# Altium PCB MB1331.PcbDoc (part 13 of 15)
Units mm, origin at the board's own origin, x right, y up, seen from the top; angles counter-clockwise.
Board outline 169.25 x 173.25 mm, 6 copper layers (Top Layer, Signal Layer 1, Signal Layer 2, Signal Layer 3, Signal Layer 4, Bottom Layer), stack 1.556 mm thick; 871 components, 699 nets, 3244 pads, 2370 vias.
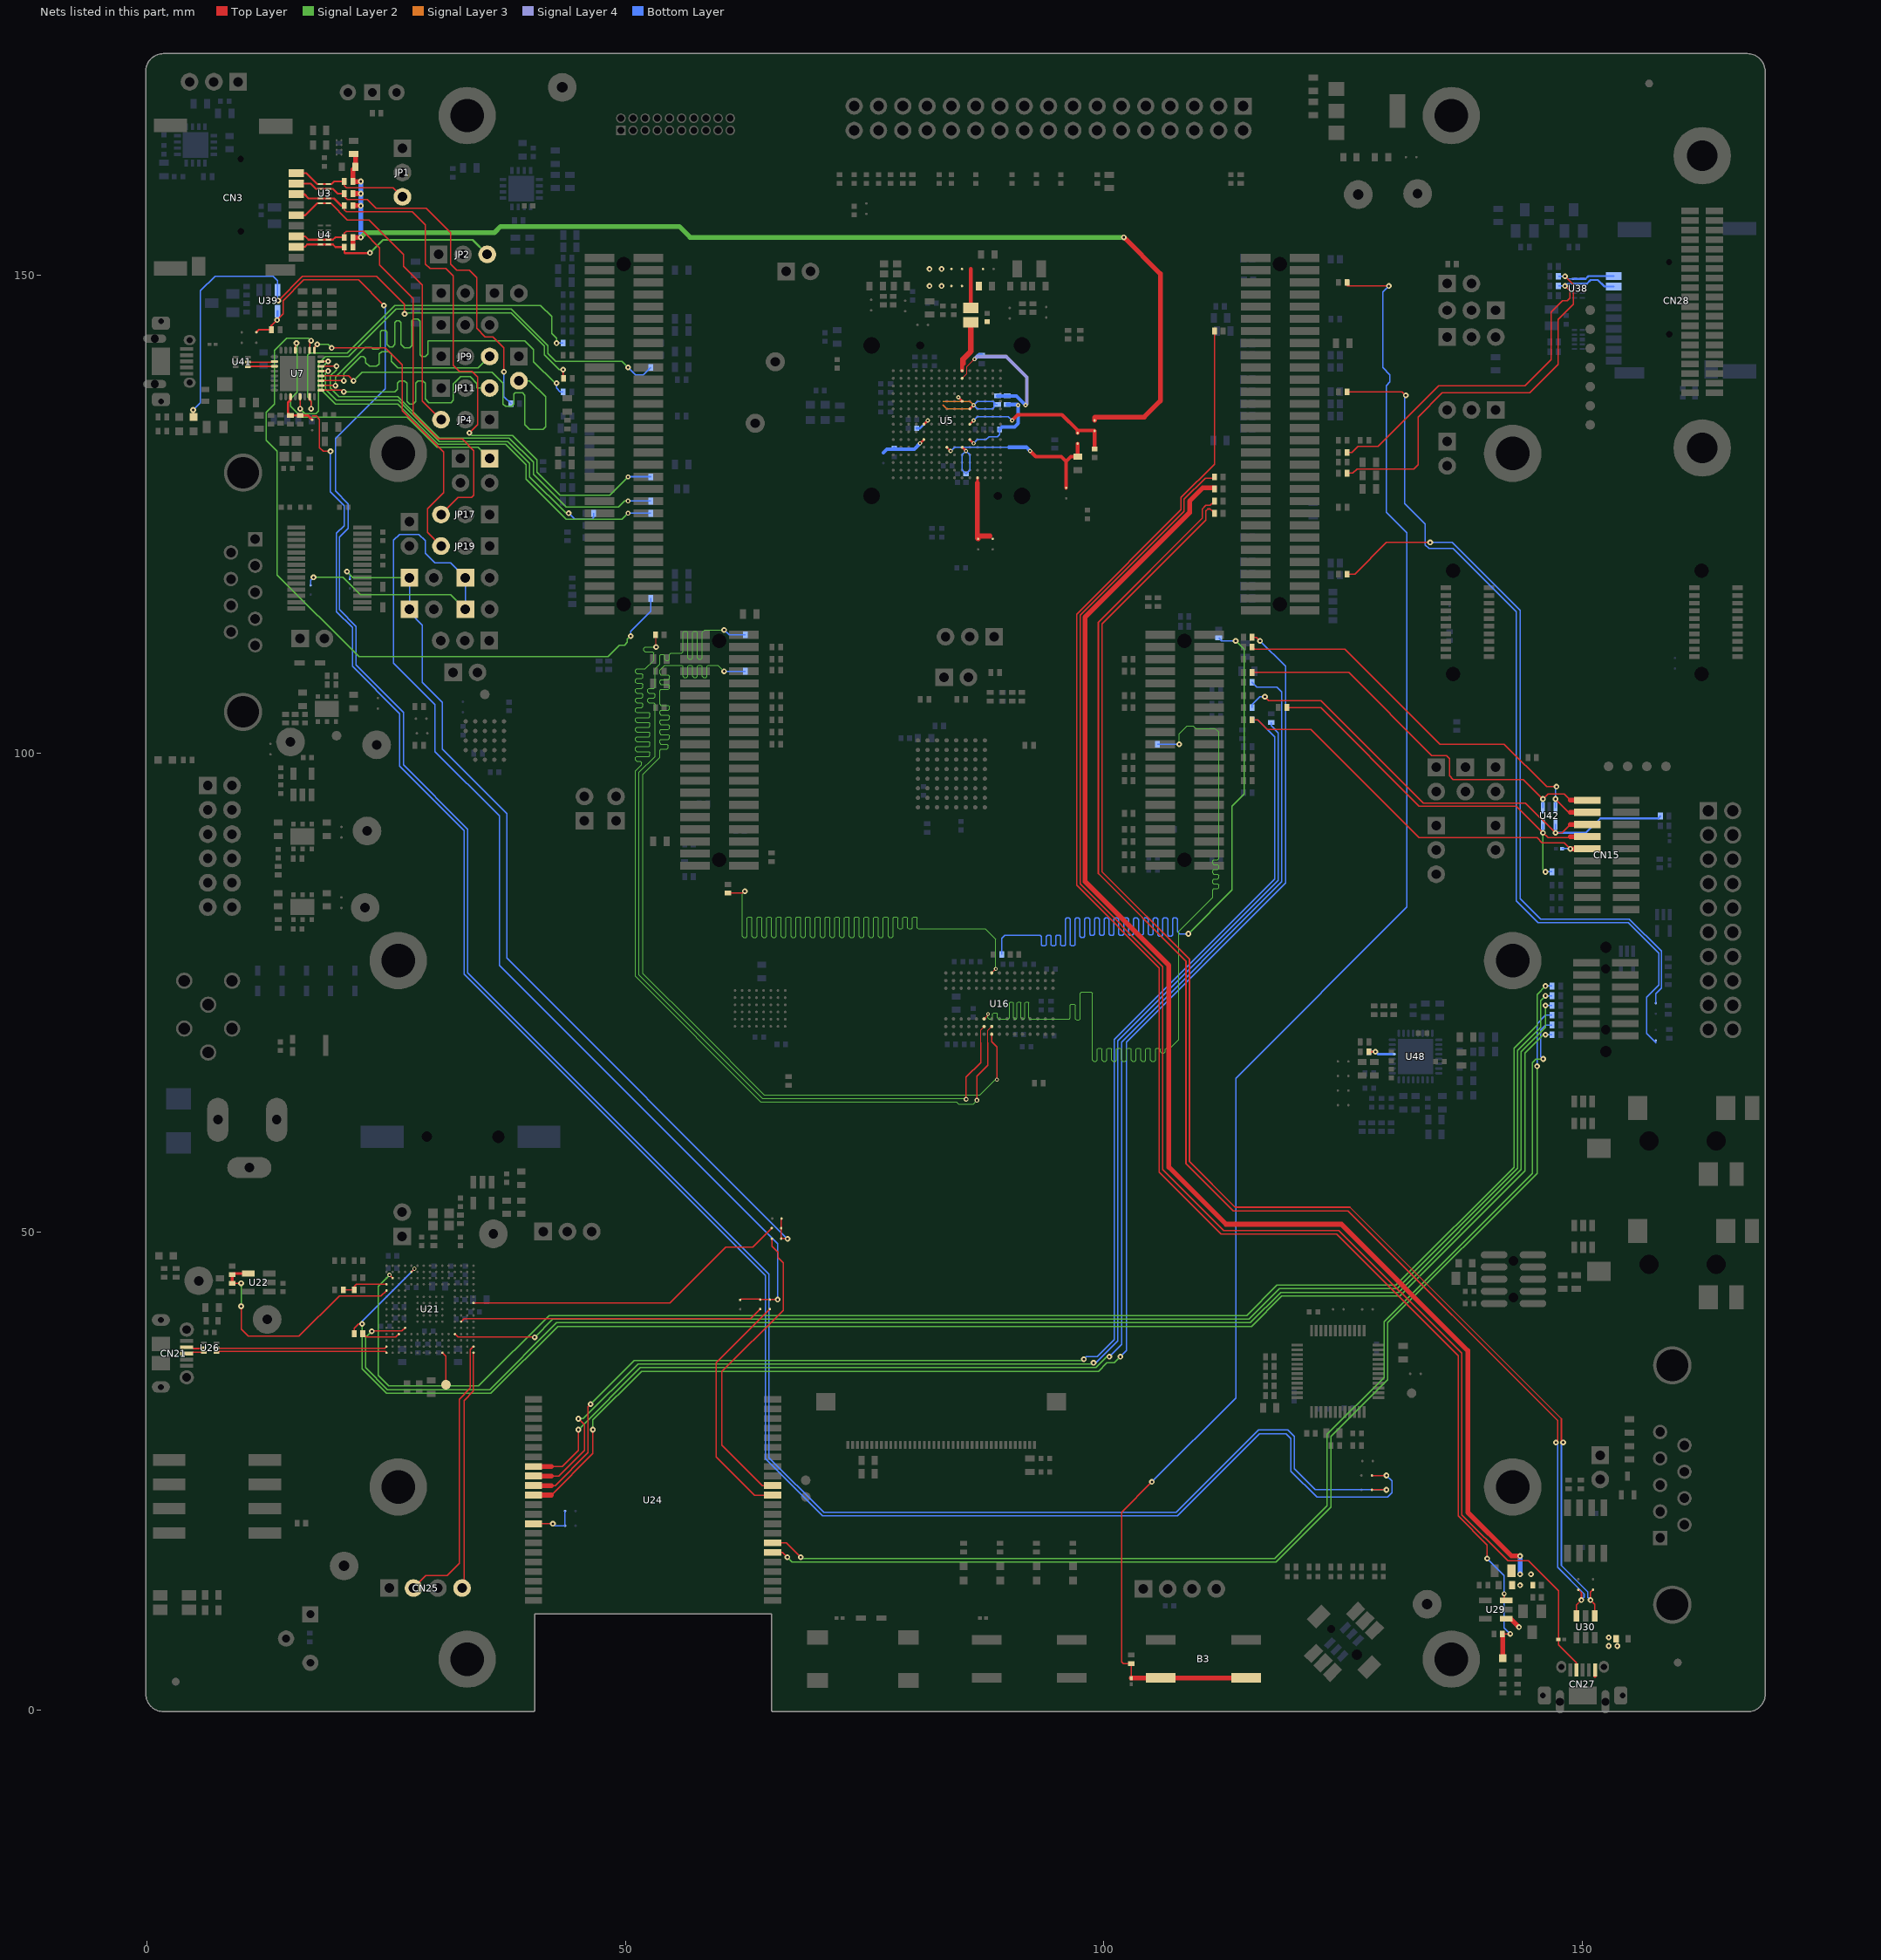
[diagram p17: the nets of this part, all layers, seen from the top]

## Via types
v1: diameter 0.6, hole 0.254, Top Layer to Bottom Layer, tented both sides, 1747 vias
v2: diameter 0.45, hole 0.2, Top Layer to Bottom Layer, tented both sides, 272 vias
v3: diameter 0.406, hole 0.203, Top Layer to Bottom Layer, tented both sides, 160 vias
v4: diameter 0.6, hole 0.25, Top Layer to Bottom Layer, tented both sides, 82 vias
v5: diameter 0.45, hole 0.25, Top Layer to Bottom Layer, tented both sides, 45 vias
v6: diameter 0.5, hole 0.25, Top Layer to Bottom Layer, tented both sides, 23 vias
v7: diameter 1.016, hole 0.508, Top Layer to Bottom Layer, tented both sides, 17 vias
v8: diameter 0.508, hole 0.254, Top Layer to Bottom Layer, tented both sides, 9 vias
v9: diameter 0.61, hole 0.305, Top Layer to Bottom Layer, tented both sides, 7 vias
v10: diameter 0.5, hole 0.254, Top Layer to Bottom Layer, tented both sides, 6 vias
v11: diameter 0.4, hole 0.2, Top Layer to Bottom Layer, tented both sides, 1 vias
v12: diameter 0.483, hole 0.254, Top Layer to Bottom Layer, tented both sides, 1 vias

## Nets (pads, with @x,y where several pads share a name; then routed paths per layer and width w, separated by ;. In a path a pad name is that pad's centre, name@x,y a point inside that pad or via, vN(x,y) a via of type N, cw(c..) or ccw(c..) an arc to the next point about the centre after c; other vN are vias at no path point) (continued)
SDIO1_D2: CN28.1 R56.1 R224.1 U38.5 U38.6 | length 46
  Top Layer w0.127: R56.1@125.418,129.286 126.047,129.286 126.492,129.731 132.398,129.731 132.842,130.175 132.842,135.128 135.382,137.668 144.526,137.668 147.511,140.653 147.511,145.351 149.098,146.939 149.098,148.971 v1(148.209,149.86)
  Bottom Layer w0.127: R224.1@147.516,149.86 v1(148.209,149.86) 148.479,149.59 U38.5@149.196,149.59
  Bottom Layer w0.203: U38.5@149.196,149.59 U38.6@150.016,149.59 150.368,149.59 150.655,149.877 CN28.1@153.301,149.877
SDIO1_D3: CN28.2 R51.1 R227.1 U38.4 U38.7 | length 40.7
  Top Layer w0.127: R51.1@125.418,131.445 125.946,131.445 126.581,132.08 128.651,132.08 135.001,138.43 144.018,138.43 146.749,141.16 146.749,146.113 147.955,147.32 148.463,147.32 148.717,147.574 148.717,148.336 v1(148.209,148.844)
  Bottom Layer w0.127: R227.1@147.516,148.844 v1(148.209,148.844) 148.455,149.09 U38.4@149.196,149.09
  Bottom Layer w0.203: U38.4@149.196,149.09 U38.7@150.016,149.09 150.495,149.09 150.884,149.479 151.638,149.479 152.34,148.777 CN28.2@153.301,148.777
SDIO2_CK: CN3.5 JP4.3 U3.1 U3.10 | length 32.8
  Top Layer w0.127: U3.1@18.952,157.496 19.179,157.496 20.95,155.725 23.224,155.725 26.8,152.149 26.8,150.925 28.775,148.95 28.775,136.835 JP4.3@30.735,134.875
  Top Layer w0.203: CN3.5@15.6,156.24 16.54,156.24 17.796,157.496 U3.10@18.132,157.496 U3.1@18.952,157.496
SDIO2_CMD: CN3.3 R12.1 R289.2 U3.2 U3.9 | length 64.3
  Top Layer w0.127: R12.1@20.632,157.226 20.632,156.787 20.828,156.591 27.734,156.591 29.11,155.215 29.11,151.15 29.585,150.675 31.225,150.675 32,149.9 32,140.575 32.647,139.928 33.947,139.928 34.544,139.331 34.544,135.906 34.55,135.9 34.55,134.35 v1(33.7,133.5)
  Top Layer w0.203: CN3.3@15.6,158.44 16.439,158.44 16.883,157.996 U3.9@18.132,157.996 U3.2@18.952,157.996 19.55,157.996 20.32,157.226 R12.1@20.632,157.226
  Signal Layer 2 w0.127: v1(33.7,133.5) 33.7,133.505 33.703,133.503 33.982,133.223 38.227,133.223 40.767,130.683 40.767,129.413 43.18,127 48.387,127 v6(50.292,128.905)
  Bottom Layer w0.2: v6(50.292,128.905) R289.2@52.636,128.905
SDIO2_D0: CN3.7 JP17.3 R13.1 U4.2 U4.9 | length 45.8
  Top Layer w0.127: R13.1@20.632,153.924 20.632,154.363 20.828,154.559 22.606,154.559 24.325,152.84 24.325,151.025 27.813,147.537 27.813,135.509 30.48,132.842 32.957,132.842 34.163,131.636 34.163,127 33.909,126.746 32.512,126.746 JP17.3@30.734,124.968
  Top Layer w0.2: CN3.7@15.6,154.04 16.51,154.04 16.872,153.678 U4.9@18.132,153.678 U4.2@18.952,153.678 19.431,153.678 19.677,153.924 R13.1@20.632,153.924
SDIO2_D1: CN3.8 JP2.3 R14.1 U4.1 U4.10 | length 22
  Top Layer w0.203: CN3.8@15.6,152.94 16.51,152.94 16.748,153.178 U4.10@18.132,153.178 U4.1@18.952,153.178 19.431,153.178 19.701,152.908 R14.1@20.632,152.908 20.632,152.342 20.701,152.273 23.273,152.273 v1(23.3,152.3)
  Signal Layer 2 w0.203: v1(23.3,152.3) 24.67,153.67 34.036,153.67 JP2.3@35.56,152.146
SDIO2_D2: CN3.1 JP1.3 R10.1 U3.5 U3.6 | length 12.6
  Top Layer w0.127: R10.1@20.632,159.766 20.632,159.327 20.828,159.131 25.729,159.131 JP1.3@26.7,158.16
  Top Layer w0.203: CN3.1@15.6,160.64 16.652,160.64 17.796,159.496 U3.6@18.132,159.496 U3.5@18.952,159.496 19.304,159.496 19.574,159.766 R10.1@20.632,159.766
SDIO2_D3: CN3.2 R11.1 R122.1 U3.4 U3.7 | length 40.2
  Top Layer w0.127: R11.1@20.624,158.496 20.624,158.192 20.955,157.861 23.039,157.861 23.928,156.972 29.178,156.972 31.725,154.425 31.725,151.125 32.375,150.475 33.7,150.475 34.462,149.713 34.462,144.413 35.35,143.525 36.15,143.525 37.312,142.363 v1(37.312,139.875)
  Top Layer w0.203: CN3.2@15.6,159.54 17.117,159.54 17.661,158.996 U3.7@18.132,158.996 U3.4@18.952,158.996 19.439,158.996 19.939,158.496 20.624,158.496 R11.1@20.632,158.496
  Bottom Layer w0.127: v1(37.312,139.875) 37.312,137.288 R122.1@38.05,136.55
SDOUT_C: R140.1 R413.1 U48.29 | length 3.3
  Top Layer w0.254: R140.1@127.704,68.834 v1(128.397,68.834)
  Bottom Layer w0.254: R413.1@127.704,68.834 v1(128.397,68.834) 128.655,68.576 U48.29@130.163,68.576
SDR_CKE1: R320.1 R397.1 | length 105.1
  Signal Layer 2 w0.127: v1(108.839,81.153) 113.411,85.725 113.411,94.488 114.681,95.758 114.681,110.871 v1(113.792,111.76)
  Bottom Layer w0.127: R397.1@89.35,78.994 89.35,80.689 89.662,81.001 93.345,81.001 93.472,80.874 93.472,80.01 93.599,79.883 93.853,79.883 93.98,80.01 93.98,80.874 94.107,81.001 94.386,81.001 94.488,80.899 94.488,80.01 94.615,79.883 94.869,79.883 94.996,80.01 94.996,80.899 95.098,81.001 95.402,81.001 95.504,80.899 95.504,80.01 95.631,79.883 95.885,79.883 96.012,80.01 96.012,82.677 96.139,82.804 96.366,82.804 96.493,82.677 96.493,80.01 96.62,79.883 96.874,79.883 97.001,80.01 97.001,82.677 97.128,82.804 97.382,82.804 97.509,82.677 97.509,80.899 97.636,80.772 97.89,80.772 98.017,80.899 98.017,82.677 98.144,82.804 98.398,82.804 98.525,82.677 98.525,81.128 98.652,81.001 98.906,81.001 99.033,81.128 99.033,82.677 99.16,82.804 99.414,82.804 99.541,82.677 99.541,81.128 99.668,81.001 99.922,81.001 100.049,81.128 100.049,82.677 100.176,82.804 100.43,82.804 100.557,82.677 100.557,81.128 100.684,81.001 100.938,81.001 101.065,81.128 101.065,82.677 101.192,82.804 101.446,82.804 101.573,82.677 101.573,81.128 101.7,81.001 101.954,81.001 102.081,81.128 102.081,82.677 102.208,82.804 102.462,82.804 102.589,82.677 102.589,81.128 102.716,81.001 102.97,81.001 103.097,81.128 103.097,82.677 103.224,82.804 103.478,82.804 103.632,82.65 103.632,81.153 103.759,81.026 104.013,81.026 104.14,81.153 104.14,82.677 104.267,82.804 104.521,82.804 104.648,82.677 104.648,81.153 104.775,81.026 105.029,81.026 105.156,81.153 105.156,82.677 105.283,82.804 105.537,82.804 105.664,82.677 105.664,81.026 105.791,80.899 106.045,80.899 106.172,81.026 106.172,82.677 106.299,82.804 106.553,82.804 106.68,82.677 106.68,81.026 106.807,80.899 107.061,80.899 107.188,81.026 107.188,82.677 107.315,82.804 107.569,82.804 107.696,82.677 107.696,81.407 107.95,81.153 v1(108.839,81.153) ; R320.1@112.014,112.072 112.326,111.76 v1(113.792,111.76)
SDR_CLK: R132.1 U16.J1 | length 105.3
  Top Layer w0.102: v1@62.288,85.402 v1(62.484,85.598) ; U16.J1@88.297,77.063 v3(88.716,77.482)
  Top Layer w0.127: R132.1@60.706,85.402 v1@62.288,85.402
  Signal Layer 2 w0.102: v1(62.484,85.598) 62.23,85.344 62.23,80.899 62.357,80.772 62.611,80.772 62.738,80.899 62.738,82.804 62.865,82.931 63.119,82.931 63.246,82.804 63.246,80.899 63.373,80.772 63.627,80.772 63.754,80.899 63.754,82.804 63.881,82.931 64.135,82.931 64.262,82.804 64.262,80.899 64.389,80.772 64.643,80.772 64.77,80.899 64.77,82.804 64.897,82.931 65.151,82.931 65.278,82.804 65.278,80.899 65.405,80.772 65.659,80.772 65.786,80.899 65.786,82.804 65.913,82.931 66.167,82.931 66.294,82.804 66.294,80.899 66.421,80.772 66.675,80.772 66.802,80.899 66.802,82.804 66.929,82.931 67.183,82.931 67.31,82.804 67.31,80.899 67.437,80.772 67.691,80.772 67.818,80.899 67.818,82.829 67.92,82.931 68.224,82.931 68.326,82.829 68.326,80.899 68.453,80.772 68.707,80.772 68.834,80.899 68.834,82.829 68.936,82.931 69.215,82.931 69.342,82.804 69.342,80.899 69.469,80.772 69.723,80.772 69.85,80.899 69.85,82.804 69.977,82.931 70.231,82.931 70.358,82.804 70.358,80.899 70.485,80.772 70.739,80.772 70.866,80.899 70.866,82.804 70.993,82.931 71.247,82.931 71.374,82.804 71.374,80.899 71.501,80.772 71.755,80.772 71.882,80.899 71.882,82.804 72.009,82.931 72.263,82.931 72.39,82.804 72.39,80.899 72.517,80.772 72.771,80.772 72.898,80.899 72.898,82.804 73.025,82.931 73.279,82.931 73.406,82.804 73.406,80.899 73.533,80.772 73.787,80.772 73.914,80.899 73.914,82.804 74.041,82.931 74.295,82.931 74.422,82.804 74.422,80.899 74.549,80.772 74.803,80.772 74.93,80.899 74.93,82.804 75.057,82.931 75.311,82.931 75.438,82.804 75.438,80.899 75.565,80.772 75.819,80.772 75.946,80.899 75.946,82.804 76.073,82.931 76.327,82.931 76.454,82.804 76.454,80.899 76.581,80.772 76.835,80.772 76.962,80.899 76.962,82.804 77.089,82.931 77.343,82.931 77.47,82.804 77.47,80.899 77.597,80.772 77.851,80.772 77.978,80.899 77.978,82.804 78.105,82.931 78.359,82.931 78.486,82.804 78.486,81.788 78.613,81.661 78.867,81.661 78.994,81.788 78.994,82.804 79.121,82.931 79.375,82.931 79.502,82.804 79.502,81.788 79.629,81.661 79.883,81.661 80.01,81.788 80.01,82.804 80.137,82.931 80.391,82.931 80.518,82.804 80.518,81.788 80.645,81.661 87.63,81.661 88.716,80.575 v3(88.716,77.482)
SDR_NCAS: R352.1 U16.K7 | length 107.2
  Top Layer w0.102: U16.K7@87.497,72.263 87.903,72.67 v3(87.903,72.771)
  Signal Layer 2 w0.102: v3(87.903,72.771) 87.903,72.371 88.011,72.263 88.265,72.263 88.392,72.39 88.392,72.771 88.519,72.898 88.773,72.898 88.9,72.771 88.9,72.39 89.027,72.263 90.04,72.263 90.142,72.365 90.142,73.94 90.244,74.041 90.447,74.041 90.548,73.94 90.548,72.365 90.65,72.263 90.853,72.263 90.955,72.365 90.955,73.94 91.056,74.041 91.26,74.041 91.361,73.94 91.361,72.365 91.463,72.263 91.666,72.263 91.768,72.365 91.768,73.94 91.869,74.041 92.072,74.041 92.174,73.94 92.174,72.365 92.276,72.263 96.4,72.263 96.502,72.365 96.502,73.711 96.604,73.813 96.926,73.813 97.028,73.711 97.028,72.263 97.155,72.136 97.409,72.136 97.536,72.263 97.536,74.93 97.663,75.057 98.552,75.057 98.679,75.057 98.806,74.93 98.806,67.945 98.933,67.818 99.187,67.818 99.314,67.945 99.314,69.088 99.441,69.215 99.695,69.215 99.822,69.088 99.822,67.945 99.949,67.818 100.203,67.818 100.33,67.945 100.33,69.088 100.457,69.215 100.711,69.215 100.838,69.088 100.838,67.945 100.965,67.818 101.219,67.818 101.346,67.945 101.346,69.088 101.473,69.215 101.727,69.215 101.854,69.088 101.854,67.945 101.981,67.818 102.235,67.818 102.362,67.945 102.362,69.088 102.489,69.215 102.743,69.215 102.87,69.088 102.87,67.945 102.997,67.818 103.251,67.818 103.378,67.945 103.378,69.088 103.505,69.215 103.759,69.215 103.886,69.088 103.886,67.945 104.013,67.818 104.267,67.818 104.394,67.945 104.394,69.088 104.521,69.215 104.775,69.215 104.902,69.088 104.902,67.945 105.029,67.818 105.283,67.818 105.41,67.945 105.41,69.088 105.537,69.215 105.791,69.215 105.918,69.088 105.918,68.834 106.045,68.707 106.299,68.707 106.426,68.834 106.426,69.088 106.553,69.215 106.934,69.215 107.823,70.104 107.823,81.407 111.379,84.963 111.379,85.725 111.506,85.852 111.887,85.852 112.014,85.979 112.014,86.233 111.887,86.36 111.506,86.36 111.379,86.487 111.379,86.741 111.506,86.868 111.887,86.868 112.014,86.995 112.014,87.249 111.887,87.376 111.506,87.376 111.379,87.503 111.379,87.757 111.506,87.884 111.887,87.884 112.014,88.011 112.014,88.265 111.887,88.392 111.506,88.392 111.379,88.519 111.379,88.773 111.506,88.9 111.887,88.9 112.014,89.027 112.014,102.235 111.633,102.616 109.601,102.616 109.347,102.87 108.712,102.87 107.886,102.044 v1(107.886,100.965)
  Bottom Layer w0.127: R352.1@105.606,100.965 v1(107.886,100.965)
SDR_NE1: R68.1 U16.J8 | length 108.2
  Top Layer w0.102: R68.1@53.144,112.395 53.144,111.194 v1(53.213,111.125) ; 87.89,69.781 87.89,71.057 U16.J8@88.297,71.463
  Top Layer w0.127: v8(86.741,63.754) 86.741,66.288 87.89,67.437 87.89,69.781
  Signal Layer 2 w0.102: v1(53.213,111.125) 52.07,111.125 51.943,110.998 51.943,110.744 52.07,110.617 52.832,110.617 52.959,110.49 52.959,109.728 52.07,108.839 51.181,108.839 51.054,108.712 51.054,108.458 51.181,108.331 51.689,108.331 51.816,108.204 51.816,107.95 51.689,107.823 51.181,107.823 51.054,107.696 51.054,107.442 51.181,107.315 51.689,107.315 51.816,107.188 51.816,106.934 51.689,106.807 51.181,106.807 51.054,106.68 51.054,106.426 51.181,106.299 51.689,106.299 51.816,106.172 51.816,105.918 51.689,105.791 51.181,105.791 51.054,105.664 51.054,105.41 51.181,105.283 51.689,105.283 51.816,105.156 51.816,104.902 51.689,104.775 51.181,104.775 51.054,104.648 51.054,104.394 51.181,104.267 52.451,104.267 52.578,104.14 52.578,103.886 52.451,103.759 51.181,103.759 51.054,103.632 51.054,103.378 51.181,103.251 52.451,103.251 52.578,103.124 52.578,102.87 52.451,102.743 51.181,102.743 51.054,102.616 51.054,102.362 51.181,102.235 52.451,102.235 52.578,102.108 52.578,101.854 52.451,101.727 51.181,101.727 51.054,101.6 51.054,101.346 51.181,101.219 52.451,101.219 52.578,101.092 52.578,100.838 52.451,100.711 51.181,100.711 51.054,100.584 51.054,100.33 51.181,100.203 52.451,100.203 52.578,100.076 52.578,99.822 52.451,99.695 51.181,99.695 51.054,99.568 51.054,99.314 51.181,99.187 51.562,99.187 51.689,99.06 51.689,98.806 51.054,98.171 51.054,76.702 63.747,64.008 64.154,63.602 84.601,63.602 84.829,63.373 86.36,63.373 v8(86.741,63.754)
SDR_NRAS: R332.2 U16.J9 | length 108.4
  Top Layer w0.127: U16.J9@88.297,70.663 88.296,69.863 88.843,69.317 v3(88.843,65.913)
  Signal Layer 2 w0.102: v1(60.325,108.585) 59.69,109.22 58.674,109.22 58.547,109.093 58.547,108.077 58.42,107.95 58.166,107.95 58.039,108.077 58.039,109.093 57.912,109.22 57.658,109.22 57.531,109.093 57.531,108.077 57.404,107.95 57.15,107.95 57.023,108.077 57.023,109.093 56.896,109.22 56.642,109.22 56.515,109.093 56.515,108.077 56.388,107.95 56.134,107.95 56.007,108.077 56.007,109.093 55.88,109.22 54.102,109.22 53.594,108.712 53.594,108.331 53.721,108.204 54.483,108.204 54.61,108.077 54.61,107.823 54.483,107.696 53.721,107.696 53.594,107.569 53.594,107.315 53.721,107.188 54.483,107.188 54.61,107.061 54.61,106.807 54.483,106.68 53.721,106.68 53.594,106.553 53.594,105.156 53.721,105.029 54.483,105.029 54.61,104.902 54.61,104.648 54.483,104.521 53.721,104.521 53.594,104.394 53.594,104.14 53.721,104.013 54.483,104.013 54.61,103.886 54.61,103.632 54.483,103.505 53.721,103.505 53.594,103.378 53.594,103.124 53.721,102.997 54.483,102.997 54.61,102.87 54.61,102.616 54.483,102.489 53.721,102.489 53.594,102.362 53.594,102.108 53.721,101.981 54.483,101.981 54.61,101.854 54.61,101.6 54.483,101.473 53.721,101.473 53.594,101.346 53.594,101.092 53.721,100.965 54.356,100.965 54.483,100.838 54.483,100.584 54.356,100.457 53.721,100.457 53.594,100.33 53.594,99.568 51.816,97.79 51.816,77.007 57.553,71.269 64.281,64.542 64.509,64.313 87.065,64.313 88.665,65.913 v3(88.843,65.913)
  Bottom Layer w0.127: v1(60.325,108.585) R332.2@62.542,108.585
SDR_NWE: R322.1 U16.K8 | length 108.3
  Top Layer w0.102: 87.141,69.781 87.141,71.108 U16.K8@87.497,71.463
  Top Layer w0.127: v8(85.617,63.856) 85.617,66.167 87.141,67.691 87.141,69.781
  Signal Layer 2 w0.102: v1(60.325,112.903) 58.293,112.903 58.039,112.649 58.039,109.982 57.912,109.855 57.658,109.855 57.531,109.982 57.531,112.649 57.404,112.776 57.15,112.776 57.023,112.649 57.023,109.982 56.896,109.855 56.642,109.855 56.515,109.982 56.515,112.649 56.388,112.776 56.134,112.776 56.007,112.649 56.007,110.617 55.88,110.49 54.737,110.49 54.61,110.363 54.61,109.855 54.483,109.728 54.229,109.728 54.102,109.855 54.102,110.236 53.975,110.363 53.721,110.363 53.594,110.236 53.594,109.347 53.086,108.839 53.086,106.934 52.959,106.807 52.451,106.807 52.324,106.68 52.324,106.426 52.451,106.299 52.959,106.299 53.086,106.172 53.086,105.918 52.959,105.791 52.451,105.791 52.324,105.664 52.324,105.41 52.451,105.283 52.959,105.283 53.086,105.156 53.086,99.695 51.435,98.044 51.435,76.829 64.001,64.262 64.306,63.957 85.515,63.957 v8(85.617,63.856)
  Bottom Layer w0.127: v1(60.325,112.903) 60.833,112.395 R322.1@62.542,112.395
STLK_MCO: TP22.1 U21.F15 | length 3.5
  Top Layer w0.127: U21.F15@30.875,37.375 31.242,37.008 TP22.1@31.242,34.036
STLK_SWCLK: CN25.2 U21.A14 | length 29.1
  Top Layer w0.127: CN25.2@27.855,12.787 29.155,14.087 31.369,14.087 32.639,15.357 32.639,32.512 33.8,33.673 33.8,37.7 U21.A14@34.125,38.025
STLK_SWDIO: CN25.4 U21.A15 | length 25.1
  Top Layer w0.127: CN25.4@32.935,12.787 33.147,12.999 33.147,32.385 34.125,33.363 U21.A15@34.125,37.375
STLK_VCP_RX: SB42.1 U21.C10 | length 31.8
  Top Layer w0.127: U21.C10@32.825,40.625 33.15,40.95 63.1,40.95 SB42.1@64.1,41.95
STLK_VCP_TX: SB41.1 U21.A7 | length 34.4
  Top Layer w0.127: U21.A7@34.125,42.575 54.675,42.575 60.5,48.4 63.3,48.4 SB41.1@65.3,50.4
T_NRSTa: R398.1 U21.P3 | length 161.1
  Top Layer w0.127: v2(25.35,45.5) U21.P3@25.675,45.175
  Signal Layer 2 w0.127: v2(25.35,45.5) 24.166,44.317 24.166,35.016 25.273,33.909 34.671,33.909 42.037,41.275 114.935,41.275 118.11,44.45 130.556,44.45 142.875,56.769 142.875,69.215 145.288,71.628 145.288,74.803 v1(146.177,75.692)
  Bottom Layer w0.127: v1(146.177,75.692) R398.1@146.87,75.692
T_PWR_EN: R148.1 R152.1 U21.R5 U22.4 | length 25.8
  Top Layer w0.127: R152.1@8.89,44.646 v1(9.837,44.646) ; v1(9.837,42.233) 9.837,39.863 10.605,39.095 15.888,39.095 20.1,43.307 24.457,43.307 U21.R5@25.025,43.875
  Top Layer w0.3: R152.1@8.89,44.646 R148.1@8.89,45.524 9.02,45.654 U22.4@10.584,45.654
  Signal Layer 2 w0.127: v1(9.837,42.233) v1(9.837,44.646)
T_PWR_EXT: R153.1 R154.2 U21.R4 | length 5
  Top Layer w0.127: R153.1@20.516,43.942 R154.2@21.648,43.942 21.648,44.298 21.875,44.525 U21.R4@25.025,44.525
T_SWCLKa: R401.1 U21.M11 | length 157.8
  Top Layer w0.127: v1(23.495,39.624) 23.521,39.65 26.65,39.65 U21.M11@26.975,39.975
  Signal Layer 2 w0.127: v1(23.495,39.624) 22.86,38.989 22.86,35.814 25.146,33.528 35.814,33.528 42.799,40.513 115.316,40.513 118.491,43.688 130.81,43.688 143.637,56.515 143.637,68.834 146.177,71.374 v1(146.177,73.66)
  Bottom Layer w0.127: v1(146.177,73.66) R401.1@146.87,73.66
T_SWDIO_IN: R157.1 U21.N12 | length 4.1
  Top Layer w0.127: R157.1@22.548,39.37 22.918,39 26,39 U21.N12@26.325,39.325
T_SWDIOa: R157.2 R409.1 U21.L2 | length 163
  Top Layer w0.127: R157.2@21.648,39.37 21.648,39.936 22.098,40.386 v1(22.479,40.386) ; U21.L2@27.625,45.825 v5(27.95,46.15)
  Signal Layer 2 w0.127: v1(22.479,40.386) 22.479,35.687 25.019,33.147 35.941,33.147 42.926,40.132 115.443,40.132 118.618,43.307 130.937,43.307 144.018,56.388 144.018,68.707 145.923,70.612 v1(146.177,70.612)
  Bottom Layer w0.127: v1(22.479,40.386) 22.479,40.679 v5(27.95,46.15) ; v1(146.177,70.612) R409.1@146.87,70.612
T_SWOa: R399.1 U21.D12 | length 138.5
  Top Layer w0.127: U21.D12@32.175,39.325 32.5,39 40.502,39 v4(40.513,38.989)
  Signal Layer 2 w0.127: v4(40.513,38.989) 42.418,40.894 115.189,40.894 118.364,44.069 130.683,44.069 143.256,56.642 143.256,68.961 145.669,71.374 145.669,74.168 v1(146.177,74.676)
  Bottom Layer w0.127: v1(146.177,74.676) R399.1@146.87,74.676
T_VCP_RX: JP20.1 JP39.1 SB41.2 SB48.2 SB49.2 SB52.2 | length 96.6
  Top Layer w0.127: SB52.2@66.325,51.4 66.275,51.35 SB41.2@66.275,50.4 SB48.2@66.275,49.3 66.919,49.3 v1(66.95,49.269) v1@66.719,49.269
  Signal Layer 2 w0.127: v1(20.9,119) 21.536,118.364 JP20.1@27.432,118.364 ; JP39.1@27.094,115.4 JP39.1@27.432,115.062
  Bottom Layer w0.127: v1(20.9,119) 21.2,118.7 SB49.2@21.2,118.225 ; JP20.1@27.432,118.364 JP39.1@27.432,115.062 27.432,114.752 28.784,113.4 28.784,107.417 30.861,105.339 30.861,100.457 37.592,93.726 37.592,78.608 v1@66.91,49.291
T_VCP_TX: JP21.1 JP40.1 SB42.2 SB47.2 SB50.2 SB51.1 | length 132
  Top Layer w0.127: SB51.1@62,42.9 62.108,43.008 64.1,43.008 SB42.2@64.1,42.925 SB47.2@65.1,42.925 ; SB47.2@65.1,42.9 65.126,42.926 v1(65.913,42.926)
  Signal Layer 2 w0.127: v1(17.4,118.4) 20.5,118.4 22.3,116.6 31.736,116.6 JP40.1@33.274,115.062
  Bottom Layer w0.127: SB50.2@17.1,117.575 17.1,118.1 v1(17.4,118.4) ; JP40.1@33.274,115.062 JP21.1@33.274,118.364 31.738,119.9 30.1,119.9 29.1,120.9 29.1,122.221 28.421,122.9 26.381,122.9 25.781,122.3 25.781,109.419 30.099,105.101 30.099,100.203 36.83,93.472 36.83,77.851 65.913,48.768 v1(65.913,42.926)
TAMPER_KEY: B3.1 B3.2 R16.1 R194.1 U35.1 | length 177.1
  Top Layer w0.127: U35.1@102.87,3.36 R194.1@102.87,4.884 102.05,4.884 101.854,5.08 101.854,20.701 v4(105.029,23.876) ; R16.1@125.418,149.225 125.418,148.902 125.476,148.844 v1(129.794,148.844)
  Top Layer w0.508: U35.1@102.899,3.39 B3.2@105.968,3.39 B3.1@114.868,3.39
  Bottom Layer w0.127: v4(105.029,23.876) 113.792,32.639 113.792,66.04 131.699,83.947 131.699,123.063 129.54,125.222 129.54,138.43 129.921,138.811 129.921,139.573 129.159,140.335 129.159,148.209 v1(129.794,148.844)
TRACECLK: CN15.12 R101.1 U44.1 | length 41.3
  Top Layer w0.127: R101.1@115.762,103.505 116.078,103.505 117.094,102.489 121.666,102.489 132.969,91.186 145.288,91.186 145.796,90.678 148.128,90.678 v1(148.771,90.035)
  Top Layer w0.508: v1(148.771,90.035) CN15.12@150.538,90.035
  Bottom Layer w0.127: U44.1@147.886,90.043 148.763,90.043 v1(148.771,90.035) v1@148.711,89.974
TRACED0: CN15.14 R93.1 R390.1 U42.5 | length 42.9
  Top Layer w0.127: R93.1@119.15,104.775 122.682,104.775 132.969,94.488 143.129,94.488 v1(145.908,91.709) 146.431,91.186 148.652,91.186 148.771,91.305
  Top Layer w0.508: 148.771,91.305 CN15.14@150.538,91.305
  Signal Layer 2 w0.127: v1(145.908,91.709) 145.908,87.899 v1(146.177,87.63)
  Bottom Layer w0.127: v1(145.908,91.709) U42.5@145.908,92.622 ; v1(146.177,87.63) R390.1@146.87,87.63
TRACED1: CN15.16 R340.1 R372.1 U42.4 | length 54.5
  Top Layer w0.127: v1(116.84,105.918) 117.221,105.537 122.682,105.537 133.395,94.824 144.094,94.824 v1(147.208,91.709) 147.905,91.709 148.771,92.575
  Top Layer w0.508: 148.771,92.575 CN15.16@150.538,92.575
  Bottom Layer w0.127: R340.1@115.512,104.775 115.512,105.098 116.332,105.918 v1(116.84,105.918) ; v1(147.208,91.709) U42.4@147.208,92.622
  Bottom Layer w0.2: v1(147.208,91.709) 150.391,91.709 151.9,93.218 157.943,93.218 R372.1@158.178,93.453
TRACED2: CN15.18 R71.1 U42.3 | length 44
  Top Layer w0.127: R71.1@115.512,111.125 115.766,110.871 125.222,110.871 135.128,100.965 141.859,100.965 146.304,96.52 v1(147.32,96.52) ; v1(147.208,95.235) 148.598,93.845 148.771,93.845
  Top Layer w0.508: 148.771,93.845 CN15.18@150.538,93.845
  Bottom Layer w0.127: U42.3@147.208,94.322 v1(147.208,95.235) 147.208,96.408 v1(147.32,96.52)
TRACED3: CN15.20 R80.1 U42.1 | length 42.9
  Top Layer w0.127: R80.1@115.512,108.458 125.603,108.458 134.281,99.78 135.805,99.78 136.144,99.441 136.144,97.663 136.525,97.282 143.861,97.282 v1(145.908,95.235) 146.431,95.758 148.128,95.758 148.771,95.115
  Top Layer w0.508: 148.771,95.115 CN15.20@150.538,95.115
  Bottom Layer w0.127: U42.1@145.908,94.322 v1(145.908,95.235)
TRGIN: R64.1 SB43.2 | length 75.2
  Top Layer w0.127: R64.1@125.418,118.745 126.238,118.745 129.54,122.047 v1(134.112,122.047)
  Bottom Layer w0.127: v1(134.112,122.047) 136.398,122.047 143.51,114.935 143.51,84.836 145.669,82.677 154.94,82.677 158.28,79.337 158.28,75.48 157.7,74.9 SB43.2@157.7,73.9
TRGOUT: R34.1 SB44.2 | length 93
  Top Layer w0.127: R34.1@125.418,137.795 131.191,137.795 v1(131.572,137.414)
  Bottom Layer w0.127: v1(131.572,137.414) 131.445,137.287 131.445,126.111 133.604,123.952 133.604,121.793 133.985,121.412 136.525,121.412 143.129,114.808 143.129,84.582 145.415,82.296 154.813,82.296 158,79.109 158,75.8 156.736,74.536 156.736,70.764 157.742,69.758
ULPI_CK: JP11.3 U7.1 | length 27.6
  Top Layer w0.127: U7.1@18.173,137.95 20.419,137.95 v1(20.574,137.795)
  Signal Layer 2 w0.127: v1(20.574,137.795) 25.908,137.795 26.162,138.049 26.162,138.684 26.416,138.938 26.924,138.938 27.178,138.684 27.178,136.779 27.432,136.525 27.813,136.525 28.067,136.779 28.067,138.684 28.321,138.938 28.829,138.938 29.083,138.684 29.083,137.033 29.464,136.652 31.771,136.652 32.025,136.906 32.025,138.608 32.782,139.364 33.766,139.364 34.462,138.668 34.462,138.176 JP11.3@35.814,138.176
ULPI_D0: JP9.3 U7.3 | length 22.7
  Top Layer w0.127: U7.3@18.173,138.95 v1@20.574,138.95
  Signal Layer 2 w0.127: v1(20.574,138.938) 20.574,139.7 22.352,141.478 22.606,141.478 22.86,141.224 22.86,140.843 23.241,140.462 24.003,140.462 24.257,140.716 24.257,141.732 24.511,141.986 25.273,141.986 25.527,141.732 25.527,140.97 26.222,140.275 34.611,140.275 JP9.3@35.814,141.478
ULPI_D1: JP10.2 U7.4 | length 38.1
  Top Layer w0.127: U7.4@18.173,139.45 21.078,139.45 v1(21.59,138.938)
  Signal Layer 2 w0.127: v1(21.59,138.938) 22.479,139.827 36.068,139.827 37.211,138.684 37.211,136.525 37.465,136.271 38.1,136.271 38.354,136.525 38.354,137.541 38.481,137.668 39.243,137.668 39.497,137.414 39.497,134.366 40.005,133.858 41.402,133.858 41.656,134.112 41.656,137.287 40.005,138.938 JP10.2@38.862,138.938
ULPI_D2: R296.1 U7.5 | length 37.7
  Top Layer w0.127: U7.5@18.173,139.95 v1@18.919,139.95
  Signal Layer 2 w0.127: v1(18.923,139.954) 18.669,139.7 18.669,138.049 19.812,136.906 26.244,136.906 30.562,132.588 37.719,132.588 40.005,130.302 40.005,128.905 43.815,125.095 v1(44.069,125.095)
  Bottom Layer w0.127: v1(44.069,125.095) 44.704,124.46 46.482,124.46 46.678,124.656 R296.1@46.678,125.095
ULPI_D3: R292.1 U7.6 | length 43.8
  Top Layer w0.127: U7.6@18.173,140.45 19.8,140.45 v4(19.812,140.462)
  Signal Layer 2 w0.127: v4(19.812,140.462) 19.812,140.081 19.177,139.446 19.177,138.176 20.066,137.287 26.238,137.287 30.556,132.969 37.846,132.969 40.386,130.429 40.386,129.159 43.815,125.73 49.276,125.73 49.911,126.365 v6(50.292,126.365)
  Bottom Layer w0.127: v6(50.292,126.365) R292.1@52.636,126.365
ULPI_D4: R295.1 U7.7 | length 45.1
  Top Layer w0.127: U7.7@18.173,140.95 18.903,140.95 v4(18.923,140.97)
  Signal Layer 2 w0.127: v4(18.923,140.97) 18.288,140.335 18.288,137.922 19.685,136.525 26.2,136.525 30.391,132.334 37.465,132.334 39.624,130.175 39.624,128.651 43.815,124.46 49.657,124.46 v6(50.292,125.095)
  Bottom Layer w0.127: v6(50.292,125.095) R295.1@52.636,125.095
ULPI_D5: JP19.3 U7.9 | length 32.5
  Top Layer w0.127: U7.9@17.498,142.125 17.498,142.466 v1(17.78,142.748) ; v1(19.304,142.367) 24.892,142.367 26.67,140.589 26.67,135.805 30.988,131.487 30.988,127.254 29.3,125.566 29.3,123.1 JP19.3@30.734,121.666
  Signal Layer 2 w0.127: v1(17.78,142.748) 18.923,142.748 v1(19.304,142.367)
ULPI_D6: R316.1 U7.10 | length 76.2
  Top Layer w0.127: U7.10@16.998,142.125 16.998,142.982 v1(17.145,143.129)
  Signal Layer 2 w0.127: v1(17.145,143.129) 16.891,143.383 14.605,143.383 13.335,142.113 13.335,136.525 12.446,135.636 12.446,132.715 13.589,131.572 13.589,118.656 22.145,110.1 48.169,110.1 49.365,111.297 49.897,111.297 50.2,111.6 50.2,111.922 v4(50.546,112.268)
  Bottom Layer w0.127: v4(50.546,112.268) 50.546,112.776 52.636,114.866 R316.1@52.636,116.205
ULPI_D7: JP16.1 U7.13 | length 30.8
  Top Layer w0.127: U7.13@15.498,142.125 15.498,142.752 v1(15.621,142.875)
  Signal Layer 2 w0.127: v1(15.621,142.875) 15.699,142.797 15.699,137.746 14.986,137.033 14.986,136.271 16.129,135.128 27.172,135.128 30.3,132 34.624,132 JP16.1@35.814,130.81
ULPI_DIR: R245.1 U7.31 | length 38.9
  Top Layer w0.127: U7.31@16.998,137.275 16.998,136.926 17.145,136.779 v1(17.145,136.017)
  Signal Layer 2 w0.127: v1(17.145,136.017) 17.145,136.906 16.764,137.287 16.764,141.605 17.018,141.859 20.955,141.859 25.908,146.812 41.144,146.812 42.3,145.656 42.3,143.9 42.799,143.401 v1(42.799,142.875)
  Bottom Layer w0.127: v1(42.799,142.875) R245.1@43.492,142.875
ULPI_NXT: R261.1 U7.2 | length 46.9
  Top Layer w0.127: U7.2@18.173,138.45 19.665,138.45 v1(19.685,138.43)
  Signal Layer 2 w0.127: v1(19.685,138.43) 19.685,139.319 22.783,142.417 23.433,142.417 23.625,142.225 24.175,142.225 24.4,142.45 24.4,144.05 24.55,144.2 24.925,144.2 25.094,144.031 25.094,142.75 25.35,142.494 25.654,142.494 25.908,142.748 25.908,145.034 26.099,145.225 26.352,145.225 26.543,145.034 26.543,142.748 26.924,142.367 27.432,142.367 27.686,142.621 27.686,145.211 27.875,145.4 28.3,145.4 28.367,145.334 28.525,145.175 28.525,141.675 28.722,141.478 29.103,141.478 29.35,141.725 29.35,143.05 29.429,143.129 39.471,143.129 40.412,142.188 40.412,140.944 42.672,138.684 v1(42.799,138.684)
  Bottom Layer w0.127: v1(42.799,138.684) 42.799,138.176 43.18,137.795 R261.1@43.492,137.795
ULPI_STP: R255.1 U7.29 | length 49.2
  Top Layer w0.127: v4@15.998,136.021 v4(16.002,136.017) 16.002,136.648 15.998,136.652 U7.29@15.998,137.275
  Signal Layer 2 w0.127: v4(16.002,136.017) 16.51,135.509 17.653,135.509 17.907,135.763 17.907,140.716 18.669,141.478 21.082,141.478 26.035,146.431 38.069,146.431 41.9,142.6 41.9,141.775 42.705,140.97 49.657,140.97 v1(50.292,140.335)
  Bottom Layer w0.127: v1(50.292,140.335) 51.054,139.573 51.874,139.573 R255.1@52.636,140.335
USB_DEV_HS_CN_N: CN21.2 U26.5 | length 1.9
  Top Layer w0.155: CN21.2@4.15,37.95 4.699,37.95 4.834,37.815 5.588,37.815 5.672,37.9 U26.5@5.95,37.9
USB_DEV_HS_CN_P: CN21.3 U26.6 | length 1.9
  Top Layer w0.155: CN21.3@4.15,37.3 4.691,37.3 4.826,37.435 5.915,37.435 U26.6@5.95,37.4
USB_DEV_HS_N: U21.R14 U26.2 | length 17.9
  Top Layer w0.155: U26.2@7.25,37.9 7.439,37.9 7.498,37.841 24.84,37.841 U21.R14@25.025,38.025
USB_DEV_HS_P: U21.R15 U26.1 | length 17.9
  Top Layer w0.155: U26.1@7.25,37.4 7.449,37.4 7.558,37.51 24.891,37.51 U21.R15@25.025,37.375
USB_HS_N: U7.19 U41.1 | length 2.8
  Top Layer w0.155: U41.1@10.556,140.412 10.594,140.45 U7.19@13.323,140.45
USB_HS_P: U7.18 U41.2 | length 2.8
  Top Layer w0.155: U41.2@10.556,140.912 10.593,140.875 13.248,140.875 U7.18@13.323,140.95
USB_HS_PHY_RESET: R40.2 R41.1 SB13.1 SB31.1 U7.27 | length 214.6
  Top Layer w0.127: 17.272,135.255 17.683,135.255 18.034,134.904 18.034,131.953 18.415,131.572 v1(19.177,131.572) ; SB31.1@128.025,24.55 v1(129.55,24.55)
  Top Layer w0.254: U7.27@14.998,137.275 14.998,136.918 14.732,136.652 14.732,135.578 R40.2@14.986,135.324 R41.1@16.002,135.324 16.814,135.324 SB13.1@17.272,134.866
  Bottom Layer w0.127: v1(19.177,131.572) 19.177,127.323 20.6,125.9 20.6,123.8 19.8,123 19.8,114.82 21.463,113.157 21.463,109.122 26.416,104.169 26.416,98.679 33.147,91.948 33.147,76.962 64.643,45.466 64.643,26.289 70.612,20.32 107.696,20.32 116.276,28.9 119.05,28.9 119.55,28.4 119.55,25 122.275,22.275 129.65,22.275 130.125,22.75 130.125,23.975 v1(129.55,24.55)
USB_OTG_FS_ID: CN27.4 R58.1 U34.1 | length 160.7
  Top Layer w0.127: R58.1@111.564,128.778 110.617,128.778 108.394,126.555 108.394,125.285 97.536,114.427 97.536,86.36 106.172,77.724 106.172,56.515 112.522,50.165 124.587,50.165 137.414,37.338 137.414,20.447 142.24,15.621 144.399,15.621 147.516,12.504 U34.1@147.516,7.417 147.516,6.866 149.405,4.976 CN27.4@149.405,4.23
USB_OTG_FS_N: R63.1 SB36.2 U30.1 | length 150.9
  Top Layer w0.155: R63.1@111.564,125.095 111.12,125.539 110.871,125.539 110.68,125.349 110.68,124.396 99.822,113.538 99.822,87.63 108.966,78.486 108.966,57.34 113.728,52.578 125.73,52.578 147.828,30.48 147.828,28.194 v1(148.018,28.003) ; SB36.2@151.13,12.608 150.876,12.354 v1(150.876,11.525) 151.318,11.083 U30.1@151.318,9.888 U30.1@151.318,9.837
  Bottom Layer w0.155: v1(148.018,28.003) 147.828,27.813 147.828,15.145 150.59,12.383 150.59,11.811 v1(150.876,11.525)
USB_OTG_FS_OVCR: LD10.2 R29.1 R193.1 U29.3 | length 172.1
  Top Layer w0.127: R29.1@111.564,144.145 111.564,130.233 108.077,126.746 108.077,125.476 97.155,114.554 97.155,86.233 105.791,77.597 105.791,56.261 112.268,49.784 124.333,49.784 137.033,37.084 137.033,20.32 140.081,17.272 v4(140.081,15.875) ; R193.1@141.674,8.001 v1(142.494,8.001) ; v6(141.859,12.2) 141.859,11.702 U29.3@142.07,11.491
  Top Layer w0.508: R193.1@141.674,8.001 141.697,7.978 LD10.2@141.697,5.455
  Bottom Layer w0.127: v4(140.081,15.875) 141.859,14.097 v6(141.859,12.2) 141.859,8.636 v1(142.494,8.001)
USB_OTG_FS_P: R61.1 SB35.2 U30.3 | length 151.6
  Top Layer w0.155: R61.1@111.564,126.365 111.12,125.92 110.68,125.92 110.299,125.539 110.299,124.587 99.441,113.728 99.441,87.439 108.585,78.295 108.585,57.15 113.538,52.197 125.539,52.197 147.447,30.29 147.447,28.194 v4(147.256,28.003) ; U30.3@149.418,9.837 U30.3@149.418,9.888 149.418,11.02 v1(149.923,11.525) 149.923,12.291 SB35.2@149.606,12.608
  Bottom Layer w0.155: v4(147.256,28.003) 147.447,27.813 147.447,14.954 150.209,12.192 150.209,11.811 v1(149.923,11.525)
USB_OTG_FS_VBUS: C85.2 CN27.1 R60.1 R182.1 R189.1 U29.1 U33.1 | length 148.6
  Top Layer w0.381: CN27.1@151.355,3.585 CN27.1@151.355,4.23
  Top Layer w0.508: R60.1@111.564,127.762 110.363,127.762 108.966,126.365 108.966,125.158 98.044,114.236 98.044,86.614 106.807,77.851 106.807,56.769 112.776,50.8 124.841,50.8 138.049,37.592 138.049,20.701 142.621,16.129 v4(143.51,16.129) ; U29.1@142.07,9.591 142.509,9.591 v1(143.4,8.7)
  Bottom Layer w0.508: v1(143.51,14.224) v4(143.51,16.129)
  other v1: 152.781,6.731 153.67,6.731 152.781,7.62 143.51,13.081 144.653,14.224
USB_OTG_HS_OVCR: LD5.2 R108.1 U39.3 | length 61.5
  Top Layer w0.127: v1(4.826,135.89) 4.865,135.851 LD5.2@4.865,135.165 ; v1(13.716,147.32) 16.256,149.86 23.99,149.86 26.924,146.926 v1(26.924,145.923) ; v1(43.5,140.1) 43.5,139.25 R108.1@43.55,139.2
  Signal Layer 2 w0.127: v1(26.924,145.923) 27.051,146.05 38.05,146.05 41.529,142.571 41.529,141.671 43.1,140.1 v1(43.5,140.1)
  Bottom Layer w0.127: v1(4.826,135.89) 5.588,136.652 5.588,148.336 7.112,149.86 13.208,149.86 13.65,149.418 U39.3@13.65,148.42 13.65,147.386 v1(13.716,147.32)
USB_OTG_HS_PWR_EN: R28.1 SB12.1 SB32.1 U39.4 | length 237.5
  Top Layer w0.127: v1(13.589,145.288) 14.224,145.923 14.224,147.32 16.383,149.479 22.098,149.479 v1(24.765,146.812) ; SB32.1@128.025,23.05 v1(129.55,23.05)
  Top Layer w0.203: SB12.1@11.43,144.01 11.692,144.272 R28.1@13.012,144.272 13.012,144.711 v1(13.589,145.288)
  Bottom Layer w0.127: v1(24.765,146.812) 24.892,146.685 24.892,138.117 19.685,132.91 19.685,127.415 21.024,126.076 21.024,123.524 20.1,122.6 20.1,115.028 21.844,113.284 21.844,109.256 26.797,104.303 26.797,98.806 33.528,92.075 33.528,77.089 65.024,45.593 65.024,26.416 70.739,20.701 107.569,20.701 116.193,29.325 119.225,29.325 119.933,28.617 119.933,25.242 122.125,23.05 v1(129.55,23.05)
  Bottom Layer w0.203: v1(13.589,145.288) 13.65,145.349 U39.4@13.65,146.22
VCAP: C121.1 C126.1 R263.1 SB5.1 U5.E6 U5.F11 U5.L8 | length 21.3
  Top Layer w0.254: U5.L8@81.2,134.4 v2(81.6,134.8) ; U5.F11@85.2,132 v2(85.6,131.6) ; U5.E6@86,136 v2(86.4,136.4)
  Signal Layer 3 w0.127: 83.185,136.398 83.583,136 86,136 v2(86.4,136.4) 86,136.8 83.206,136.8
  Bottom Layer w0.127: R263.1@88.646,136.652 88.519,136.525 ; R263.1@88.9,136.456 88.519,136.456 ; 88.519,136.456 88.519,136.525 ; 88.519,136.456 88.519,136.127 88.392,136 86.8,136 v2(86.4,136.4) 86.8,136.8 88.498,136.8 88.519,136.779 88.519,136.525 ; 85.2,129.626 85.2,131.2 v2(85.6,131.6) 86,131.2 86,129.63 C126.1@85.598,129.228 85.2,129.626
  Bottom Layer w0.254: C121.1@80.46,133.985 80.785,133.985 v2(81.6,134.8)
  other v1: 81.788,148.844 83.058,148.844
VDD50_USB: SB17.1 SB18.1 U5.D15 | length 7.3
  Top Layer w0.254: 86.8,128.27 U5.D15@86.8,128.8
  Top Layer w0.508: 86.8,128.27 86.8,122.488 SB17.1@86.868,122.42 ; 87.168,122.72 88.092,122.72
VDD_IO_MMC: C4.2 R5.2 R10.2 R11.2 R12.2 R13.2 R14.2 SB14.1 | length 121.1
  Top Layer w0.508: R14.2@21.532,152.908 R13.2@21.532,153.924 v1(22.352,153.924) ; R12.2@21.532,157.226 v1(22.352,157.226) ; R11.2@21.532,158.496 v1(22.352,158.496) ; R5.2@21.59,162.622 21.782,162.43 C4.2@21.782,161.29 21.532,161.04 R10.2@21.532,159.766 v1(22.352,159.766) ; SB14.1@99.05,134.8 99.05,135.1 99.1,135.15 104.225,135.15 105.918,136.843 ; v1(102.108,153.924) 105.918,150.114 105.918,136.843 ; 105.918,137.475 105.918,136.843
  Signal Layer 2 w0.508: v1(22.352,153.924) 22.828,154.4 36.29,154.4 36.957,155.067 55.626,155.067 56.769,153.924 v1(102.108,153.924)
  Bottom Layer w0.508: v1(22.352,153.924) v1(22.352,157.226) v1(22.352,158.496) v1(22.352,159.766)
VDD_LDO: C122.1 C124.1 R262.1 SB3.1 SB37.1 U5.E10 U5.F5 U5.L10 | length 15.7
  Top Layer w0.254: v2(80.8,132.4) U5.L10@81.2,132.8 ; v2(84.8,137.2) U5.F5@85.2,136.8 ; U5.E10@86,132.8 v2(86.4,132.4)
  Signal Layer 3 w0.14: v2(86.4,132.4) v2@86.498,132.4
  Bottom Layer w0.127: C122.1@89.096,133.858 89.096,133.292 88.9,133.096 88.006,133.096 87.709,132.8 86.8,132.8 ; 86.8,132.8 v2(86.4,132.4) 86.8,132.8
  Bottom Layer w0.381: SB37.1@76.962,131.437 77.325,131.8 C124.1@78.2,131.8 ; C124.1@78.105,131.895 C124.1@78.2,131.8 ; v2(80.8,132.4) 80.2,131.8 C124.1@78.2,131.8 ; C122.1@89.096,133.858 89.35,134.112 90.678,134.112 91.059,134.493 v2(91.059,136.398) 91.001,136.456 R262.1@89.916,136.456
  other v1: 81.788,150.622 83.058,150.622
VDD_MMC: C35.1 SB14.2 SB15.1 U5.E8 | length 16.6
  Top Layer w0.203: U5.E8@86,134.4 v2(86.4,134.8)
  Top Layer w0.381: v2(90.424,134.8) 91.006,135.382 95.631,135.382 97.275,133.738 ; SB15.1@97.275,133.475 97.275,133.738 ; C35.1@99.05,131.825 SB14.2@99.05,133.7 99.012,133.738 97.275,133.738
  Bottom Layer w0.127: v2(86.4,134.8) 86.8,135.2 90.024,135.2 v2(90.424,134.8)
VDD_SMPS_IND_OUT: C24.2 L1.2 SB3.2 SB4.1 SB5.2 | length 3.8
  Top Layer w0.4: L1.2@86.106,146.796 86.106,150.622
VDD_SMPS_OUT: C29.2 L1.1 U5.F1 | length 5.2
  Top Layer w0.4: U5.F1@85.175,140.025 U5.F1@85.2,140 85.2,140.65 85.3,140.75
  Top Layer w0.6: 85.3,140.75 85.3,141.2 86.106,142.006 L1.1@86.106,144.796
VFBSD: R251.1 R262.2 R263.2 U5.F2 | length 16.2
  Top Layer w0.1: U5.F2@85.2,139.2 85.45,139.45 85.673,139.673 85.673,140.41 v2@86.423,141.16
  Signal Layer 4 w0.381: v2(86.5,141.2) 86.778,141.478 89.789,141.478 91.948,139.319 91.948,136.525 v2(91.821,136.398)
  Bottom Layer w0.381: v2@86.534,141.166 v2(86.5,141.2) 86.916,141.616 R251.1@87.249,141.616 ; R263.2@88.9,137.356 R262.2@89.916,137.356 90.863,137.356 v2(91.821,136.398)
VREGOUT33: C33.1 SB15.2 SB16.2 U5.H11 | length 19
  Top Layer w0.127: U5.H11@83.6,132 v2(84,131.6)
  Top Layer w0.381: v2(92.3,131.6) 92.898,131.002 95.548,131.002 96.05,130.5 ; SB16.2@96.075,127.75 96.05,127.775 96.05,130.5 ; SB15.2@97.275,132.375 C33.1@97.275,131.009 ; C33.1@97.282,131.002 C33.1@97.275,131.009 ; 96.05,130.5 96.559,131.009 C33.1@97.275,131.009
  Bottom Layer w0.127: v2(84,131.6) 84.4,132 90.1,132
  Bottom Layer w0.381: 90.1,132 91.9,132 v2(92.3,131.6)
W_JTCK: R406.2 U24.28 | length 122.5
  Top Layer w0.127: U24.28@65.4,16.5 66.431,16.5 v4(66.929,16.002)
  Signal Layer 2 w0.127: v4(66.929,16.002) 67.437,15.494 117.983,15.494 123.75,21.261 123.75,28.65 129.667,34.567 129.667,40.513 145.288,56.134 v1(145.288,67.31)
  Bottom Layer w0.127: v1(145.288,67.31) 145.288,71.755 146.177,72.644 R406.2@146.87,72.644
W_JTMS: R407.2 U24.29 | length 122
  Top Layer w0.127: U24.29@65.4,17.5 66.828,17.5 v4(68.326,16.002)
  Signal Layer 2 w0.127: v4(68.326,16.002) 68.453,15.875 117.856,15.875 123.35,21.369 123.35,28.85 129.286,34.786 129.286,40.64 144.78,56.134 144.78,67.691 145.161,68.072 v1(145.923,68.072)
  Bottom Layer w0.127: v1(145.923,68.072) 145.669,68.326 145.669,71.12 146.177,71.628 R407.2@146.87,71.628
W_NRST: SB45.1 SB46.1 U24.14 | length 4.9
  Top Layer w0.127: U24.14@40.4,19.5 v1(42.418,19.5)
  Bottom Layer w0.127: v1(42.418,19.5) 42.614,19.304 SB46.1@43.696,19.304 SB45.1@43.696,20.828
WIFI_SPI4_MISO: R69.1 U24.11 | length 153.4
  Top Layer w0.127: 42.271,22.5 46.609,26.838 v1(46.609,29.337) ; R69.1@115.512,112.141 115.951,112.141 v1(116.332,111.76)
  Top Layer w0.508: U24.11@40.4,22.5 42.271,22.5
  Signal Layer 2 w0.127: v1(46.609,29.337) 46.609,30.353 51.689,35.433 99.441,35.433 100.33,36.322 101.092,36.322 v1(101.727,36.957)
  Bottom Layer w0.127: v1(101.727,36.957) 102.362,37.592 102.362,69.85 118.999,86.487 118.999,109.093 v1(116.332,111.76)
WIFI_SPI4_MOSI: R334.1 U24.8 | length 146.7
  Top Layer w0.127: 42.271,25.5 43.407,25.5 45.085,27.178 v1(45.085,29.337)
  Top Layer w0.508: U24.8@40.4,25.5 42.271,25.5
  Signal Layer 2 w0.127: v1(45.085,29.337) 51.562,35.814 99.187,35.814 100.33,36.957 v1(100.584,36.957)
  Bottom Layer w0.127: v1(100.584,36.957) 101.854,38.227 101.854,69.85 118.618,86.614 118.618,106.426 118.11,106.934 116.02,106.934 R334.1@115.512,107.442 R334.1@115.454,107.442
WIFI_SPI4_NSS: R337.1 U24.9 | length 141.6
  Top Layer w0.127: 42.271,24.5 43.042,24.5 45.72,27.178 45.72,29.845 v1(45.085,30.48)
  Top Layer w0.508: U24.9@40.4,24.5 42.271,24.5
  Signal Layer 2 w0.127: v1(45.085,30.48) 45.593,30.48 51.308,36.195 98.806,36.195 v1(98.933,36.322)
  Bottom Layer w0.127: v1(98.933,36.322) 99.187,36.322 101.473,38.608 101.473,69.977 118.237,86.741 118.237,102.163 117.5,102.9 R337.1@117.5,103.25
WIFI_SPI4_SCK: R343.1 U24.10 | length 142.6
  Top Layer w0.127: 42.271,23.5 42.677,23.5 46.101,26.924 46.101,31.75 v1(46.355,32.004)
  Top Layer w0.508: U24.10@40.4,23.5 42.271,23.5
  Signal Layer 2 w0.127: v1(46.355,32.004) 50.927,36.576 97.79,36.576 v1(97.917,36.703)
  Bottom Layer w0.1: R343.1@115.762,103.505 116.078,103.505
  Bottom Layer w0.127: v1(97.917,36.703) 98.171,36.957 99.314,36.957 101.092,38.735 101.092,70.104 117.856,86.868 117.856,101.727 116.078,103.505
WIFI_UART_RX: SB48.1 U24.35 | length 31.8
  Top Layer w0.127: SB48.1@65.3,49.3 65.3,48.5 65.958,47.843 65.958,47.306 66.5,46.764 66.5,41.8 60.1,35.4 60.1,27.715 64.315,23.5 U24.35@65.4,23.5
WIFI_UART_TX: SB47.1 U24.34 | length 25.3
  Top Layer w0.127: SB47.1@65.1,41.925 59.5,36.325 59.5,26.5 63.5,22.5 U24.34@65.4,22.5
pads on no net: B4.NPTH1 B4.NPTH2 CART-1.1 CN2.5 CN2.6 CN2.9 CN2.10 CN3.NPTH1 CN3.NPTH2 CN5.NPTH1 CN5.NPTH2 CN6.NPTH1 CN6.NPTH2 CN8.11 CN8.12 CN9.1 CN9.4 CN9.7 CN9.9 CN10.NPTH1 CN10.NPTH2 CN11.5 CN11.6 CN11.7 CN11.8 CN11.9 CN11.10 CN11.11 CN11.12 CN11.NPTH1 CN11.NPTH2 CN12.NPTH1 CN12.NPTH2 CN13.NPTH1 CN13.NPTH2 CN15.7 CN16.0 CN16.1 CN16.2 CN16.9 CN18.5 CN18.7 CN18.MT1 CN18.MT2 CN20.2 CN20.5 CN20.7 CN20.MT1 CN20.MT2 CN21.4 CN22.1 CN22.4 CN22.8 CN24.1 CN24.3 CN24.7 CN27.11 CN27.12 CN28.NPTH1 CN28.NPTH2 CN29.NPTH1 CN29.NPTH2 CN30.NPTH1 CN30.NPTH2 MIRE-PLACE-3.1 MIRE-PLACE-4.1 MIRE-PLACE-5.1 MIRE-PLACE-6.1 MIRE-PLACE-7.1 MIRE-PLACE-8.1 U4.4 U4.5 U4.6 U4.7 U5.NPTH1 U5.NPTH2 U5.PTH1 U5.PTH2 U5.PTH3 U5.PTH4 U7.12 U7.15 U7.16 U7.25 U9.4 U9.8 U9.9 U9.11 U9.15 U9.18 U9.19 U9.21 U11.A2 U11.A3 U11.B1 U11.B5 U12.A1 U12.A8 U12.B1 U12.C1 U12.D1 U12.E1 U12.F8 U12.G1 U12.G8 U12.H1 U12.H8 U14.3 U15.3 U16.E3 U16.E7 U16.H3 U16.H7 U16.K2 U16.K3 U17.A6 U17.E3 U20.1 U21.A1 U21.A2 U21.A3 U21.A4 U21.A5 U21.A6 U21.A8 U21.A9 U21.A10 U21.A11 U21.A12 U21.A13 U21.B1 U21.B2 U21.B3 U21.B4 U21.B5 U21.B6 U21.B7 U21.B8 U21.B9 U21.B10 U21.B11 U21.B12 U21.B13 U21.B14 U21.B15 U21.C2 U21.C3 U21.C4 U21.C11 U21.C12 U21.C13 U21.C14 U21.C15 U21.D1 U21.D2 U21.D3 U21.D4 U21.D10 U21.D11 U21.D13 U21.D14 U21.E1 U21.E2 U21.E3 U21.E4 U21.E12 U21.E13 U21.E14 U21.E15 U21.F1 U21.F4 U21.F14 U21.G4 U21.G14 U21.G15 U21.H1 U21.H2 U21.H3 U21.H4 U21.H14 U21.H15 U21.J2 U21.J3 U21.J4 U21.K1 U21.K2 U21.K3 U21.K12 U21.K14 U21.K15 U21.L1 U21.L3 U21.L12 U21.L13 U21.L14 U21.L15 U21.M2 U21.M3 U21.M4 U21.M5 U21.M6 U21.M7 U21.M12 U21.M13 U21.M14 U21.M15 U21.N2 U21.N4 U21.N5 U21.N6 U21.N7 U21.N11 U21.N13 U21.N14 U21.N15 U21.P2 U21.P4 U21.P5 U21.P6 U21.P7 U21.P8 U21.P9 U21.P10 U21.P11 U21.P12 U21.P13 U21.P14 U21.P15 U21.R2 U21.R3 U21.R6 U21.R7 U21.R8 U21.R9 U21.R10 U21.R11 U21.R12 U21.R13 U24.2 U24.6 U24.7 U24.12 U24.16 U24.17 U24.18 U24.19 U24.20 U24.21 U24.22 U24.24 U24.25 U24.26 U24.27 U24.31 U24.32 U24.38 U24.44 U25.4 U25.10 U25.11 U25.12 U25.13 U25.25 U25.41 U26.4 U30.5 U36.16 U37.16 U40.4 U40.5 U40.6 U40.7 U41.4 U47.3 U48.19 U48.20

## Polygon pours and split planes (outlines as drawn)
NetC31_1 on Top Layer "NETC31_1_L01_P1089" (solid, remove dead copper, pour order 1089): 9.271,133.477 9.271,136.779 8.89,137.16 4.318,137.16 3.556,137.922 3.556,139.192 3.81,139.446 4.699,139.446 4.826,139.573 4.826,139.7 4.699,139.827 3.048,139.827 2.667,139.446 2.667,137.668 3.937,136.398 6.731,136.398 7.112,136.017 7.112,133.604 7.366,133.35 9.144,133.35
GND on Top Layer "GND_L01_P1129" (solid, remove dead copper, pour order 1129): 27.593,43.95 27.593,40.05 31.493,40.05 31.493,43.95
GND on Top Layer "GND_L01_P1134" (solid, remove dead copper, pour order 1134): 7.07,44.831 8.043,44.831 8.17,44.958 8.17,45.475 8.128,45.517 8.128,46.101 8.255,46.228 11.303,46.228 11.43,46.101 11.43,44.577 11.557,44.45 14.574,44.45 14.574,44.921 13.372,44.921 13.335,44.958 12.192,44.958 11.938,45.212 11.938,46.736 11.684,46.99 7.747,46.99 7.07,46.313
5V on Top Layer "5V_L01_P1138" (solid, remove dead copper, pour order 1138): 11.43,93.98 15.367,93.98 15.494,93.853 15.494,92.837 15.494,92.456 15.367,92.329 15.113,92.329 11.684,92.329 11.43,92.583 11.43,93.98
GND on Top Layer "GND_L01_P1140" (solid, remove dead copper, pour order 1140): 18.034,92.075 13.335,92.075 13.208,91.948 13.208,91.694 13.208,90.805 13.335,90.678 13.462,90.551 15.494,90.551 19.177,90.551 19.304,90.678 19.304,90.932 19.304,91.948 19.177,92.075 18.034,92.075
5V on Top Layer "5V_L01_P1144" (solid, remove dead copper, pour order 1144): 11.43,86.614 15.367,86.614 15.494,86.487 15.494,85.471 15.494,85.09 15.367,84.963 15.113,84.963 11.684,84.963 11.43,85.217 11.43,86.614
5V_STLK_LDO_IN on Top Layer "5V_STLK_LDO_IN_L01_P1141" (solid, remove dead copper, pour order 1141): 35.687,54.61 35.687,56.896 35.941,57.15 39.497,57.15 39.624,57.023 39.624,56.134 39.497,56.007 37.338,56.007 36.83,55.499 36.83,54.737 36.703,54.61
GND on Top Layer "GND_L01_P1139" (solid, remove dead copper, pour order 1139): 34.798,55.753 34.798,55.372 34.798,54.483 34.671,54.356 34.544,54.356 32.512,54.356 32.385,54.229 32.385,54.102 32.385,53.975 32.512,53.848 32.639,53.848 36.703,53.848 36.957,53.594 37.338,53.213 37.719,53.213 39.497,53.213 39.624,53.34 39.624,53.594 39.624,55.118 39.497,55.245 39.37,55.245 37.465,55.245 37.338,55.118 37.338,54.864 37.338,54.737 37.084,54.483 36.957,54.356 36.576,54.356 35.433,54.356 35.306,54.483 35.306,54.61 35.306,55.753 34.798,55.753
NetC50_2 on Top Layer "NETC50_2_L01_P1146" (solid, remove dead copper, pour order 1146): 16.256,93.98 20.828,93.98 21.082,93.726 21.082,92.329 16.129,92.329 16.002,92.456 16.002,93.726
VDD_SMPS_OUT on Top Layer "VDD_SMPS_OUT_L01_P1148" (solid, pour order 1148): 85.025,145.55 85.025,139.825 85.425,139.825 85.425,140.55 88.375,143.5 88.375,145.55
2V8 on Top Layer "2V8_L01_P1067" (solid, remove dead copper, pour order 1067): 132.588,163.068 134.366,163.068 134.874,162.56 134.874,161.163 134.62,160.909 132.715,160.909 132.461,161.163 132.461,162.941
GND on Top Layer "GND_L01_P1071" (solid, remove dead copper, pour order 1071): 126.238,163.703 128.397,163.703 128.651,163.449 128.651,161.925 128.397,161.671 126.111,161.671 125.984,161.798 125.984,163.449
NetC2_2 on Top Layer "NETC2_2_L01_P1078" (solid, remove dead copper, pour order 1078): 123.571,167.894 125.603,167.894 127.127,169.418 131.318,169.418 131.699,169.037 131.699,162.079 131.291,161.671 129.54,161.671 129.413,161.798 129.413,164.719 129.286,164.846 127.127,164.846 125.603,166.37 123.571,166.37 123.317,166.624 123.317,167.64
5V on Top Layer "5V_L01_P1082" (solid, remove dead copper, pour order 1082): 123.444,165.608 125.222,165.608 125.349,165.481 125.349,161.925 125.222,161.798 123.317,161.798 123.19,161.925 123.19,165.354
1V8_LDO on Top Layer "1V8_LDO_L01_P1072" (solid, remove dead copper, pour order 1072): 13.8,98.171 12.729,98.171 12.3,98.6 12.3,100 12.9,100.6 14.1,99.4 15.3,99.4 15.621,99.1 15.621,97.282 14.732,97.282 14.605,97.409 14.605,98.044 14.478,98.171 14.224,98.171
5V on Top Layer "5V_L01_P1083" (solid, remove dead copper, pour order 1083): 15.621,96.266 14.859,96.266 14.732,96.139 11.43,96.139 11.303,96.012 11.303,95.123 11.43,94.996 15.494,94.996 15.621,95.123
